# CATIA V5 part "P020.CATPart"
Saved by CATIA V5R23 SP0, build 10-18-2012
Part number: 05-LICP-T02-E-S05-P020
Definition: Entretoise came
Bounding box of the stored display mesh (mm): x -17.954 to 17.954, y 0 to 18, z -17.954 to 17.954
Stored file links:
  C:\wamp\www\COURS\CONCEPTION GMP1\TITRE 02-SEMESTRE 2\03-TP7-PRESSE MECANIQUE\eleve\P020.CATPart
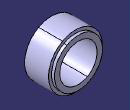
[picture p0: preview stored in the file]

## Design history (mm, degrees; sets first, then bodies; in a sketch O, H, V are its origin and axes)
Body1 (main body)
  Sketch1 on yz-plane, origin (0, 0, 0), H (0, 1, 0), V (0, 0, 1)
    point P1 (0, 12.5)
    line L1 (0, 12.5) -> (0, 18)
    line L2 (0, 18) -> (16, 18)
    line L3 (16, 18) -> (16, 16)
    line L4 (16, 16) -> (18, 16)
    line L5 (18, 16) -> (18, 12.5)
    line L6 (18, 12.5) -> (0, 12.5)
    distance H L6 = 12.5
    distance H L2 = 18
    distance L3 L1 = 16
    length L4 = 2
    distance L4 H = 16
    coincidence: P1 V
    vertical: L1 V, L3 V, L5 V
    horizontal: L2 H, L4 H, L6 H
  Shaft1: profile Sketch1, axis Sketch1.H, angle 360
